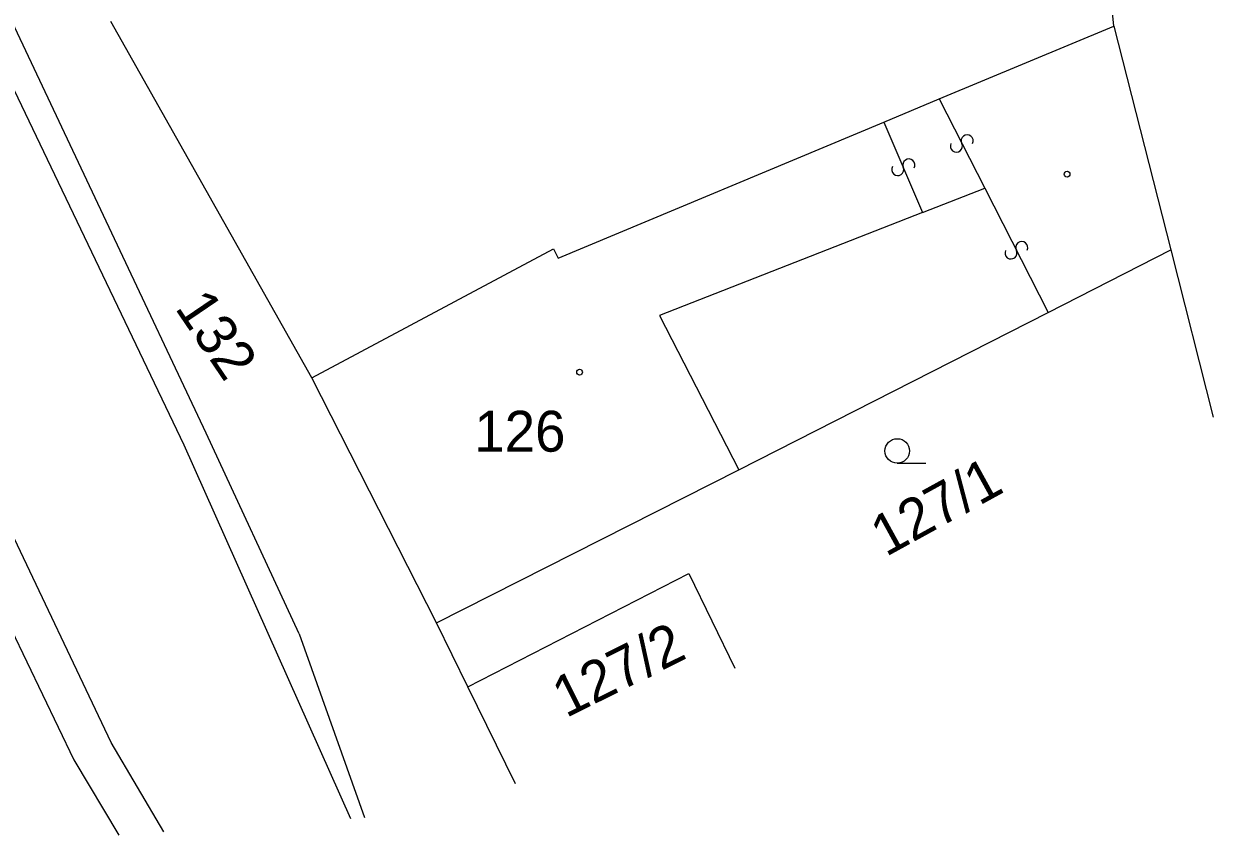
# Model space of a CAD drawing. Extents: x -595692 to -595466, y -1166896 to -1166788.
# Drawn here: x -595643.83 to -595607.45, y -1166895.97 to -1166871.15 of the extents above; entities that cross this region are included whole.
import ezdxf

# ---------------------------------------------------------------- set-up
doc = ezdxf.new("R2010")
doc.units = 0
doc.layers.add('DKM Holásky M 1_500', color=7, linetype='Continuous')

msp = doc.modelspace()

# ---------------------------------------------------------------- linework, layer by layer
at = {"layer": 'DKM Holásky M 1_500'}
for points in [[(-595610.49, -1166871.22), (-595615.67, -1166818.32)], [(-595638.25, -1166883.67), (-595661.59, -1166834.17)], [(-595662.54, -1166834.67), (-595638.93, -1166884.03)], [(-595635.02, -1166881.98), (-595641.16, -1166871.08)], [(-595615.83, -1166873.45), (-595610.49, -1166871.22)], [(-595610.49, -1166871.22), (-595608.75, -1166878.07)], [(-595617.52, -1166874.16), (-595615.83, -1166873.45)], [(-595615.83, -1166873.45), (-595614.44, -1166876.18)], [(-595627.48, -1166878.32), (-595617.52, -1166874.16)], [(-595617.52, -1166874.16), (-595616.34, -1166876.92)], [(-595616.34, -1166876.92), (-595614.44, -1166876.18)], [(-595614.44, -1166876.18), (-595612.5, -1166879.98)], [(-595616.34, -1166876.92), (-595624.38, -1166880.07)], [(-595635.02, -1166881.98), (-595627.63, -1166878.04)], [(-595627.63, -1166878.04), (-595627.48, -1166878.32)], [(-595612.5, -1166879.98), (-595608.75, -1166878.07)], [(-595608.75, -1166878.07), (-595607.451, -1166883.186)], [(-595624.38, -1166880.07), (-595621.96, -1166884.8)], [(-595621.96, -1166884.8), (-595612.5, -1166879.98)], [(-595631.21, -1166889.48), (-595635.02, -1166881.98)], [(-595635.41, -1166889.81), (-595638.25, -1166883.67)], [(-595638.93, -1166884.03), (-595633.83, -1166895.465)], [(-595617.114, -1166884.593), (-595616.239, -1166884.593)], [(-595631.21, -1166889.48), (-595621.96, -1166884.8)], [(-595641.15, -1166893.14), (-595644.41, -1166886.28)], [(-595645.66, -1166886.67), (-595642.3, -1166893.67)], [(-595630.25, -1166891.43), (-595623.49, -1166887.97)], [(-595623.49, -1166887.97), (-595622.084, -1166890.86)], [(-595630.25, -1166891.43), (-595631.21, -1166889.48)], [(-595635.41, -1166889.81), (-595633.409, -1166895.435)], [(-595628.792, -1166894.4), (-595630.25, -1166891.43)], [(-595639.539, -1166895.875), (-595641.15, -1166893.14)], [(-595642.3, -1166893.67), (-595640.923, -1166895.974)]]:
    msp.add_lwpolyline(points, dxfattribs=at)
for centre, radius in [((-595611.92, -1166875.75), 0.0875), ((-595626.829, -1166881.809), 0.0875), ((-595617.114, -1166884.218), 0.375)]:
    msp.add_circle(centre, radius, dxfattribs=at)
for centre, start, end in [((-595615.305, -1166874.892), 153.9911, 25.8705), ((-595614.975, -1166874.728), 333.4284, 206.4276), ((-595617.1, -1166875.61), 150.6434, 22.3501), ((-595616.76, -1166875.469), 330.1307, 202.6693), ((-595613.635, -1166878.162), 154.2705, 25.8692), ((-595613.306, -1166877.998), 334.0151, 206.5667)]:
    msp.add_arc(centre, 0.184, start, end, dxfattribs=at)

# ---------------------------------------------------------------- texts
for s, rotation, p in [('132', 304.2024, (-595639.226, -1166879.845)), ('127/1', 28.8002, (-595617.462, -1166887.469)), ('127/2', 26.4002, (-595627.244, -1166892.397))]:
    msp.add_text(s, height=1.25, rotation=rotation, dxfattribs=at).set_placement(p)
msp.add_text('126', height=1.25, dxfattribs=at).set_placement((-595630.05, -1166884.24))

doc.saveas('drawing.dxf')
